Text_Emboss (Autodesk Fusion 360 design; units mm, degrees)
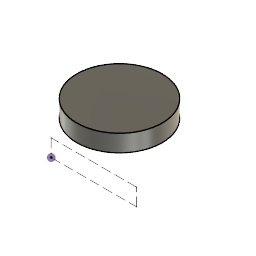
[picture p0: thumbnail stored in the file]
part number: 2026-08-31-14-48-55-015
sketch "Sketch1" plane through (0, 0, 0) normal (0, 0, 1) x axis (1, 0, 0)
  circle C1 centre (0, 0) radius 75
  point P1 (0, 0)
  point P2 (0, 0)
  coincident P1 P2
  dimension "d1" diameter C1 = 150
extrude "Extrude1" new body sketch "Sketch1" along normal blind 30
work_plane "WorkPlane1" AlongDistance -120 ExtraOffset 0
sketch "Text" plane through (0, -120, 0) normal (0, 1, 0) x axis (1, 0, 0)
  line L1 (150, 0) -> (0, 0)
  line L2 (150, -30) -> (150, 0)
  line L3 (0, -30) -> (150, -30)
  line L4 (0, 0) -> (0, -30)
  point P1 (0, 0)
  point P2 (0, 0)
  point P3 (150, 0)
  point P5 (0, -30)
  horizontal L1
  vertical L2
  horizontal L3
  vertical L4
  coincident P1 P2
  dimension "d6" distance P2 P3 = 150
  dimension "d7" distance P2 P5 = 30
